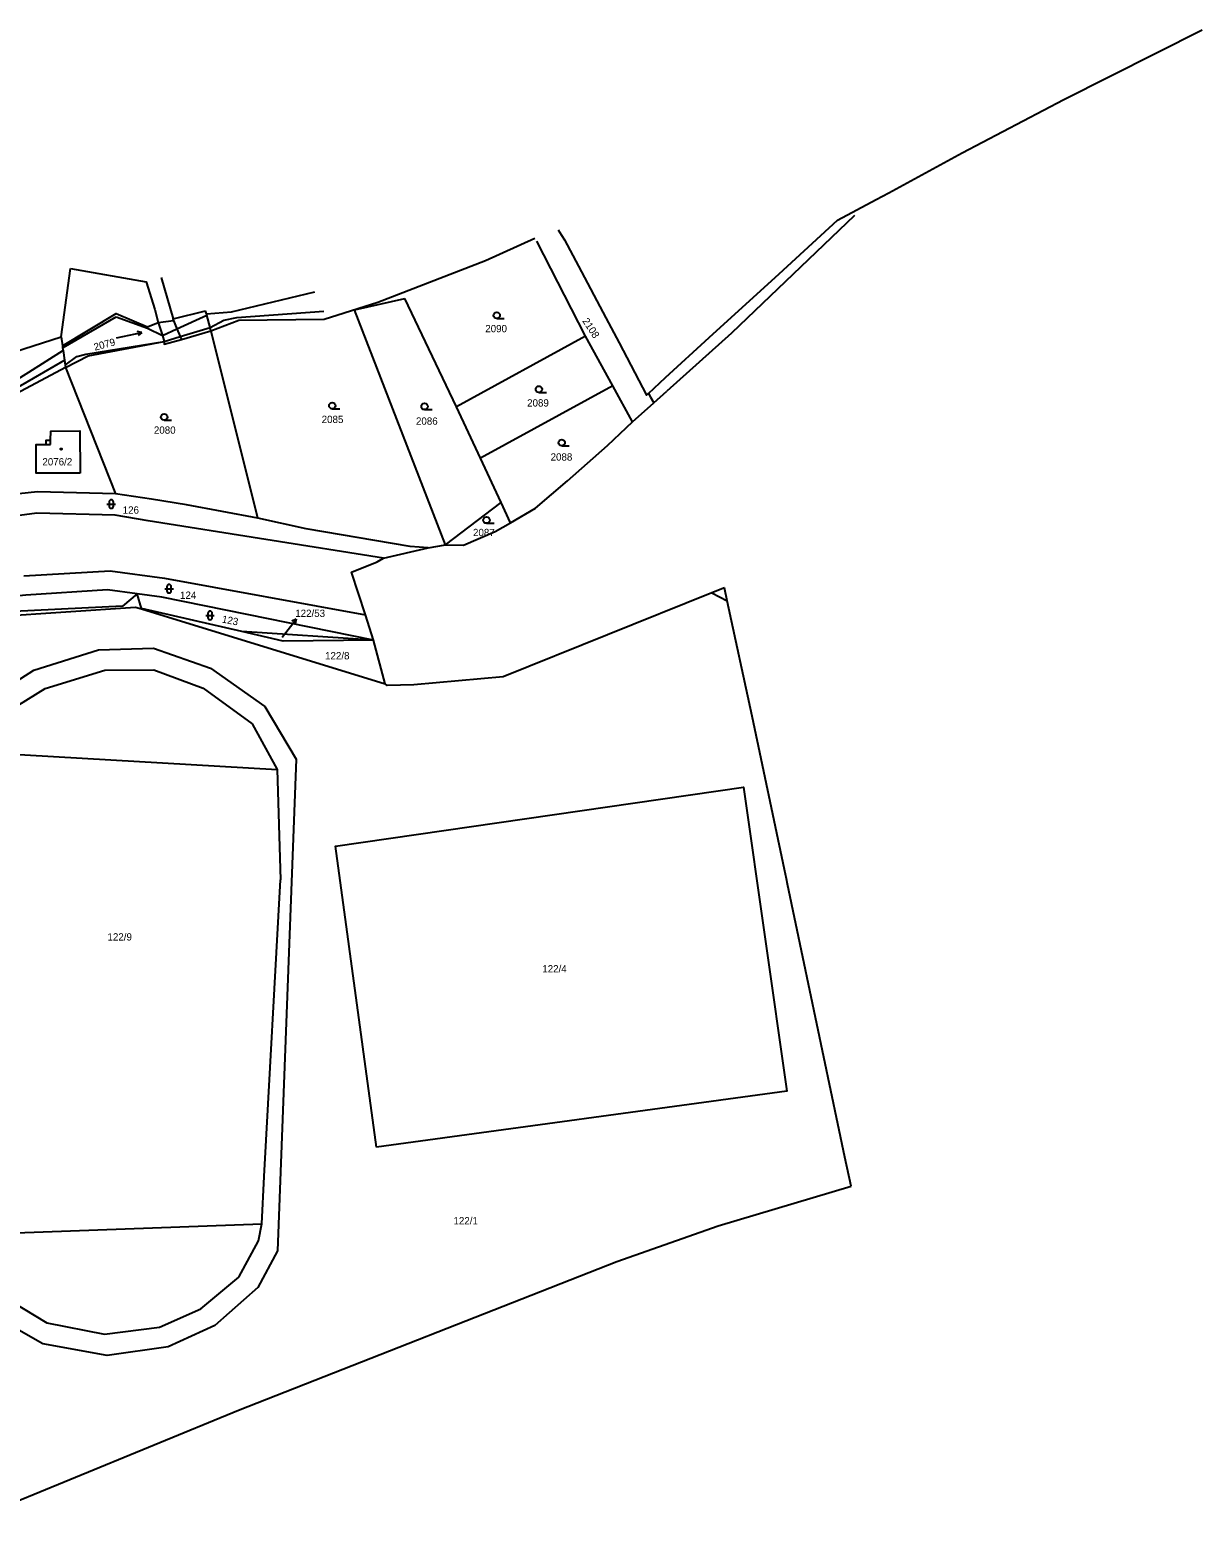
# Model space of a CAD drawing. Extents: x -783716 to -783033, y -1065203 to -1064697.
# Drawn here: x -783305.8 to -783032.6, y -1065099.3 to -1064753.3 of the extents above; entities that cross this region are included whole.
import ezdxf

# ---------------------------------------------------------------- set-up
doc = ezdxf.new("R2010")
doc.units = 0
for name, color, linetype in [('Budovy', 7, 'Continuous'), ('Doplňkové značky', 7, 'Continuous'), ('Doplňující texty', 7, 'Continuous'), ('Kultury', 7, 'Continuous'), ('Stromy_porost', 7, 'Continuous'), ('Značky IS', 7, 'Continuous')]:
    doc.layers.add(name, color=color, linetype=linetype)

msp = doc.modelspace()

# ---------------------------------------------------------------- linework, layer by layer
at = {"layer": 'Budovy'}
for p, q in [((-783113.65, -1064796.61), (-783142.24, -1064824.06)), ((-783176.27, -1064824.73), (-783187.66, -1064802.61)), ((-783298.49, -1064824.89), (-783296.26, -1064808.99)), ((-783206.32, -1064841.18), (-783218.36, -1064815.98)), ((-783264.63, -1064819.53), (-783264.82, -1064818.86)), ((-783142.24, -1064824.06), (-783157.32, -1064837.54)), ((-783298.49, -1064824.89), (-783298.18, -1064827)), ((-783176.27, -1064824.73), (-783206.32, -1064841.18)), ((-783169.91, -1064836.34), (-783176.27, -1064824.73)), ((-783298.02, -1064828.1), (-783297.7, -1064830.36)), ((-783297.44, -1064832.08), (-783285.8, -1064861.46)), ((-783169.91, -1064836.34), (-783200.77, -1064853.15)), ((-783165.34, -1064844.71), (-783169.91, -1064836.34)), ((-783160.35, -1064840.25), (-783157.32, -1064837.54)), ((-783200.77, -1064853.15), (-783206.32, -1064841.18)), ((-783165.34, -1064844.71), (-783160.35, -1064840.25)), ((-783168.18, -1064847.39), (-783165.34, -1064844.71)), ((-783195.97, -1064863.53), (-783200.77, -1064853.15)), ((-783208.93, -1064873.4), (-783195.97, -1064863.53)), ((-783193.79, -1064868.26), (-783195.97, -1064863.53)), ((-783223.32, -1064876.5), (-783212.94, -1064874.09)), ((-783212.94, -1064874.09), (-783208.93, -1064873.4)), ((-783279.77, -1064888.22), (-783280.75, -1064884.81)), ((-783146.84, -1064884.58), (-783195.49, -1064904.09)), ((-783143.94, -1064883.41), (-783146.84, -1064884.58)), ((-783143.29, -1064886.43), (-783143.94, -1064883.41)), ((-783331.24, -1064891.31), (-783281.17, -1064887.87)), ((-783281.17, -1064887.87), (-783279.74, -1064888.31)), ((-783256.38, -1064893.56), (-783279.77, -1064888.22)), ((-783279.77, -1064888.22), (-783279.74, -1064888.31)), ((-783279.74, -1064888.31), (-783222.97, -1064905.78)), ((-783225.68, -1064895.58), (-783227.58, -1064889.71)), ((-783225.68, -1064895.58), (-783256.38, -1064893.56)), ((-783222.97, -1064905.78), (-783225.68, -1064895.58)), ((-783127.27, -1064961.66), (-783129.2, -1064952.46)), ((-783115.84, -1065016.08), (-783127.27, -1064961.66)), ((-783114.42, -1065022.83), (-783115.84, -1065016.08))]:
    msp.add_line(p, q, dxfattribs=at)
for points in [[(-783161.63, -1064838.09), (-783157.62, -1064834.4), (-783147.47, -1064825.06), (-783131.16, -1064810.23), (-783117.57, -1064797.73), (-783108.58, -1064792.91), (-783105.59, -1064791.31), (-783088.53, -1064782.06), (-783064.82, -1064769.6), (-783032.58, -1064753.33)], [(-783378.92, -1064793.24), (-783353.96, -1064809.78), (-783342.78, -1064821.3), (-783318.3, -1064831.29), (-783298.49, -1064824.89)], [(-783263.56, -1064823.49), (-783257.06, -1064820.99), (-783237.2, -1064820.82), (-783224.67, -1064816.81), (-783199.61, -1064807.08), (-783188.13, -1064801.87)], [(-783182.69, -1064799.96), (-783181.9, -1064801.18), (-783181.2, -1064802.26), (-783177.94, -1064808.4), (-783171.54, -1064820.46), (-783168.48, -1064826.28), (-783162.06, -1064838.48), (-783161.63, -1064838.09)], [(-783296.26, -1064808.99), (-783278.62, -1064812.12), (-783276.67, -1064818.56), (-783275.89, -1064821.57)], [(-783298.02, -1064828.1), (-783306.05, -1064833.18), (-783311.65, -1064836.74), (-783319.29, -1064838.21), (-783322.68, -1064837.19), (-783329.49, -1064835.23), (-783335.08, -1064834.54), (-783340.03, -1064831.54), (-783346.44, -1064825.64), (-783349.95, -1064823.46), (-783352.84, -1064819.12), (-783357.07, -1064815.9), (-783358.6, -1064815.42), (-783358.65, -1064814.77), (-783360.1, -1064812.31)], [(-783264.63, -1064819.53), (-783258.74, -1064819.11), (-783239.38, -1064814.44)], [(-783208.93, -1064873.4), (-783230.12, -1064818.62), (-783218.36, -1064815.98)], [(-783298.18, -1064827), (-783285.67, -1064819.48), (-783278.31, -1064822.57), (-783275.89, -1064821.57)], [(-783275.89, -1064821.57), (-783272.26, -1064821.12), (-783272.33, -1064820.7), (-783264.82, -1064818.86)], [(-783263.56, -1064823.49), (-783263.77, -1064822.72), (-783264.55, -1064819.82), (-783264.63, -1064819.53)], [(-783297.44, -1064832.08), (-783292.2, -1064829.33), (-783274.47, -1064825.95), (-783274.43, -1064826.64), (-783270.44, -1064825.55), (-783263.56, -1064823.49)], [(-783252.64, -1064867.19), (-783263.54, -1064823.58), (-783263.56, -1064823.49)], [(-783298.18, -1064827), (-783298.12, -1064827.44), (-783298.02, -1064828.1)], [(-783378.03, -1064829.99), (-783374.76, -1064831.53), (-783372.01, -1064833.44), (-783364.04, -1064841.25), (-783357.52, -1064847.42), (-783353.19, -1064851.92), (-783349.93, -1064853.22), (-783347.61, -1064854.98), (-783346.18, -1064854.97), (-783342.54, -1064853.15), (-783328.86, -1064849.86), (-783325.75, -1064847.88), (-783320.94, -1064844.58), (-783319.53, -1064842.07), (-783314.96, -1064840.26), (-783304.91, -1064834.5), (-783297.7, -1064830.36)], [(-783297.7, -1064830.36), (-783297.53, -1064831.5), (-783297.44, -1064832.08)], [(-783297.44, -1064832.08), (-783319.38, -1064843.66), (-783326.57, -1064851.27), (-783343.73, -1064856.59), (-783345.55, -1064855.72), (-783357.76, -1064852.46), (-783360.4, -1064848.81)], [(-783161.63, -1064838.09), (-783161.13, -1064838.94), (-783160.35, -1064840.25)], [(-783294.06, -1064856.66), (-783304.25, -1064856.7), (-783304.25, -1064849.96), (-783301.96, -1064849.96), (-783301.96, -1064849), (-783300.91, -1064848.99), (-783300.88, -1064846.86), (-783294.1, -1064846.78), (-783294.06, -1064856.66)], [(-783193.79, -1064868.26), (-783187.97, -1064864.85), (-783180.48, -1064858.46), (-783171.17, -1064850.21), (-783168.18, -1064847.39)], [(-783285.8, -1064861.46), (-783303.98, -1064861.03), (-783335.87, -1064864.4), (-783335.67, -1064866.45), (-783352.38, -1064869)], [(-783252.64, -1064867.19), (-783269.29, -1064864.07), (-783277.41, -1064862.75), (-783285.8, -1064861.46)], [(-783223.32, -1064876.5), (-783278.18, -1064867.77), (-783285.91, -1064866.45), (-783304.09, -1064866.02), (-783335.01, -1064870.13), (-783384.26, -1064876.67), (-783402.03, -1064882.54), (-783402.29, -1064881.78)], [(-783212.94, -1064874.09), (-783217.15, -1064873.79), (-783241.36, -1064869.64), (-783252.64, -1064867.19)], [(-783208.93, -1064873.4), (-783204.74, -1064873.41), (-783197.37, -1064870.29), (-783193.79, -1064868.26)], [(-783307.17, -1064880.57), (-783287.03, -1064879.4), (-783274.38, -1064881.1), (-783227.58, -1064889.71)], [(-783227.58, -1064889.71), (-783230.81, -1064879.76), (-783224.85, -1064877.29), (-783223.32, -1064876.5)], [(-783280.75, -1064884.81), (-783284.2, -1064887.63), (-783339.48, -1064890.4)], [(-783280.75, -1064884.81), (-783287.64, -1064883.89), (-783306.72, -1064885.08), (-783332, -1064887.64), (-783332.16, -1064886.15)], [(-783225.68, -1064895.58), (-783274.99, -1064885.59), (-783280.75, -1064884.81)], [(-783129.92, -1064949.04), (-783137.43, -1064913.32), (-783143.29, -1064886.43)], [(-783225.68, -1064895.58), (-783246.71, -1064895.79), (-783256.38, -1064893.56)], [(-783328.17, -1064970.39), (-783326.14, -1064918.86), (-783322.67, -1064918.07), (-783317.37, -1064912.36), (-783311.76, -1064907), (-783304.84, -1064902.58), (-783289.73, -1064897.8), (-783276.94, -1064897.48), (-783263.64, -1064902.09), (-783250.99, -1064911.02), (-783243.73, -1064923.28), (-783248.06, -1065037.91), (-783252.67, -1065046.4), (-783262.68, -1065055.25), (-783273.51, -1065060.26), (-783287.72, -1065062.23), (-783302.71, -1065059.57), (-783315.49, -1065052.3), (-783324.71, -1065041.56), (-783328.14, -1065033.82), (-783330.68, -1065033.82), (-783329.69, -1065008.77)], [(-783195.49, -1064904.09), (-783216.3, -1064906.02), (-783222.52, -1064906.17), (-783222.97, -1064905.78)], [(-783224.95, -1065013.7), (-783234.55, -1064943.55), (-783139.5, -1064929.85), (-783129.35, -1065000.7), (-783224.95, -1065013.7)], [(-783129.2, -1064952.46), (-783129.47, -1064951.19), (-783129.92, -1064949.04)], [(-783316.18, -1065099.27), (-783257.14, -1065074.97), (-783168.98, -1065040.4), (-783145.36, -1065032.08), (-783114.42, -1065022.83)]]:
    msp.add_lwpolyline(points, dxfattribs=at)
at = {"layer": 'Doplňkové značky'}
for p, q in [((-783275.15, -1064811.11), (-783272.33, -1064820.7)), ((-783297.98, -1064827.39), (-783285.61, -1064820.26)), ((-783285.61, -1064820.26), (-783278.37, -1064822.88)), ((-783271.48, -1064823.03), (-783264.55, -1064819.82)), ((-783260.59, -1064820.98), (-783257.56, -1064820.39)), ((-783257.56, -1064820.39), (-783237.24, -1064818.91)), ((-783278.37, -1064822.88), (-783274.81, -1064824.57)), ((-783275.89, -1064821.57), (-783274.81, -1064824.57)), ((-783274.81, -1064824.57), (-783271.48, -1064823.03)), ((-783272.26, -1064821.12), (-783271.48, -1064823.03)), ((-783271.48, -1064823.03), (-783270.74, -1064824.82)), ((-783270.74, -1064824.82), (-783263.77, -1064822.72)), ((-783263.77, -1064822.72), (-783260.59, -1064820.98)), ((-783298.12, -1064827.44), (-783297.98, -1064827.39)), ((-783292.69, -1064828.95), (-783274.47, -1064825.95)), ((-783274.81, -1064824.57), (-783274.47, -1064825.95)), ((-783274.47, -1064825.95), (-783270.74, -1064824.82)), ((-783270.74, -1064824.82), (-783270.44, -1064825.55)), ((-783297.53, -1064831.5), (-783294.82, -1064829.51)), ((-783294.82, -1064829.51), (-783292.69, -1064828.95)), ((-783301.96, -1064849.96), (-783300.93, -1064849.96)), ((-783300.93, -1064849.96), (-783300.91, -1064848.99)), ((-783146.84, -1064884.58), (-783143.29, -1064886.43)), ((-783302.21, -1064906.83), (-783288.28, -1064902.59)), ((-783288.28, -1064902.59), (-783276.9, -1064902.48)), ((-783276.9, -1064902.48), (-783265.4, -1064906.78)), ((-783308.31, -1064910.62), (-783302.21, -1064906.83)), ((-783265.4, -1064906.78), (-783253.93, -1064915.08)), ((-783253.93, -1064915.08), (-783248.12, -1064925.69)), ((-783317.4, -1064921.73), (-783248.12, -1064925.69)), ((-783248.12, -1064925.69), (-783247.34, -1064951.46)), ((-783251.19, -1065020.56), (-783247.34, -1064951.46)), ((-783251.67, -1065031.55), (-783251.19, -1065020.56)), ((-783309.05, -1065033.7), (-783251.67, -1065031.55)), ((-783252.46, -1065035.53), (-783251.67, -1065031.55)), ((-783257.07, -1065044.02), (-783252.46, -1065035.53)), ((-783265.9, -1065051.42), (-783257.07, -1065044.02)), ((-783312.94, -1065048.01), (-783301.76, -1065054.67)), ((-783275.54, -1065055.7), (-783265.9, -1065051.42)), ((-783301.76, -1065054.67), (-783288.33, -1065057.27)), ((-783288.33, -1065057.27), (-783275.54, -1065055.7))]:
    msp.add_line(p, q, dxfattribs=at)
at = {"layer": 'Doplňující texty'}
msp.add_circle((-783298.45, -1064851.06), 0.175, dxfattribs=at)
at = {"layer": 'Kultury'}
for p, q in [((-783285.56, -1064825.16), (-783279.69, -1064823.91)), ((-783279.69, -1064823.91), (-783280.75, -1064823.62)), ((-783279.69, -1064823.91), (-783280.54, -1064824.6)), ((-783196.98, -1064820.64), (-783195.23, -1064820.64)), ((-783187.15, -1064837.87), (-783185.4, -1064837.87)), ((-783274.47, -1064844.33), (-783272.72, -1064844.33)), ((-783235.29, -1064841.7), (-783233.54, -1064841.7)), ((-783213.79, -1064841.87), (-783212.04, -1064841.87)), ((-783181.83, -1064850.31), (-783180.08, -1064850.31)), ((-783287.78, -1064863.86), (-783285.78, -1064863.86)), ((-783287.28, -1064863.36), (-783287.28, -1064864.36)), ((-783286.28, -1064864.36), (-783286.28, -1064863.36)), ((-783199.35, -1064868.35), (-783197.6, -1064868.35)), ((-783274.3, -1064883.59), (-783272.3, -1064883.59)), ((-783273.8, -1064883.09), (-783273.8, -1064884.09)), ((-783272.8, -1064884.09), (-783272.8, -1064883.09)), ((-783264.27, -1064889.31), (-783264.27, -1064890.31)), ((-783263.27, -1064890.31), (-783263.27, -1064889.31)), ((-783264.77, -1064889.81), (-783262.77, -1064889.81))]:
    msp.add_line(p, q, dxfattribs=at)
for centre in [(-783196.98, -1064819.89), (-783187.15, -1064837.12), (-783235.29, -1064840.95), (-783213.79, -1064841.12), (-783274.47, -1064843.58), (-783181.83, -1064849.56), (-783199.35, -1064867.6)]:
    msp.add_circle(centre, 0.75, dxfattribs=at)
for centre, start, end in [((-783286.78, -1064863.36), 0, 180), ((-783286.78, -1064864.36), 180, 359.9879), ((-783273.3, -1064883.09), 0, 180), ((-783273.3, -1064884.09), 180, 359.9879), ((-783263.77, -1064889.31), 0, 180), ((-783263.77, -1064890.31), 180, 359.9879)]:
    msp.add_arc(centre, 0.5, start, end, dxfattribs=at)
at = {"layer": 'Stromy_porost'}
for p, q in [((-783246.99, -1064894.86), (-783245.58, -1064893.06)), ((-783245.58, -1064893.06), (-783243.73, -1064890.7)), ((-783243.73, -1064890.7), (-783244.74, -1064891.18)), ((-783243.73, -1064890.7), (-783243.95, -1064891.79))]:
    msp.add_line(p, q, dxfattribs=at)

# ---------------------------------------------------------------- texts
at = {"layer": 'Značky IS'}
for s, rotation, p in [('2108', 303, (-783177.11, -1064821.18)), ('2079', 15, (-783290.6, -1064828.14)), ('123', 349, (-783261.11, -1064891.45))]:
    msp.add_text(s, height=1.7, rotation=rotation, dxfattribs=at).set_placement(p)
for s, p in [('2090', (-783199.64, -1064823.83)), ('2089', (-783189.89, -1064841.14)), ('2085', (-783237.76, -1064844.98)), ('2086', (-783215.79, -1064845.38)), ('2080', (-783276.85, -1064847.48)), ('2076/2', (-783302.83, -1064854.86)), ('2088', (-783184.42, -1064853.74)), ('126', (-783284.12, -1064866.1)), ('2087', (-783202.5, -1064871.34)), ('124', (-783270.76, -1064885.95)), ('122/53', (-783243.92, -1064890.17)), ('122/8', (-783236.97, -1064900.06)), ('122/9', (-783287.66, -1064965.57)), ('122/4', (-783186.36, -1064973.01)), ('122/1', (-783207.05, -1065031.71))]:
    msp.add_text(s, height=1.7, dxfattribs=at).set_placement(p)

doc.saveas('drawing.dxf')
